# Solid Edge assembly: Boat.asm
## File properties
Author: windows
Template: Iso Metric Assembly.asm
Last saved by: windows
Revision: 13
Application: Solid Edge
Username: windows
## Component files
Connector.par
Wheel.par
House.par
Tower.par
Protector.psm
Connection.psm
Stand.par
Base.par
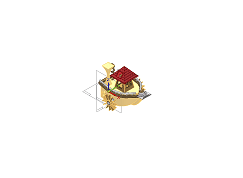
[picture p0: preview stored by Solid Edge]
